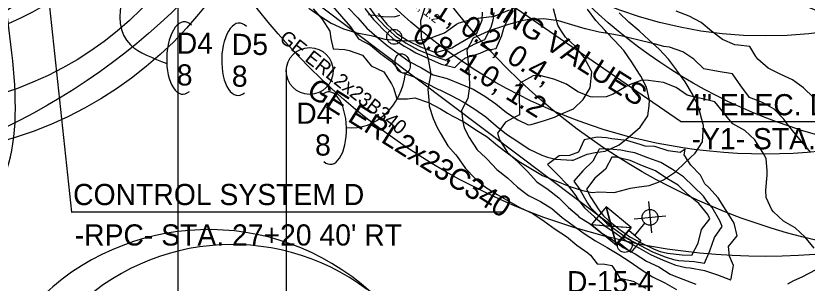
# Model space of a CAD drawing. Extents: x 1638506 to 1658005, y 834807 to 846788.
# Drawn here: x 1641459.3 to 1641907.6, y 841855.2 to 842006.7 of the extents above; entities that cross this region are included whole.
import ezdxf

# ---------------------------------------------------------------- set-up
doc = ezdxf.new("R2010")
doc.units = 0
for name, color, linetype in [('Default', 7, 'Continuous'), ('Old_Level_1', 7, 'Continuous'), ('Old_Level_4', 7, 'Continuous'), ('Scratch_Level_0', 7, 'Continuous'), ('Sheet North Arrow CELL', 7, 'Continuous')]:
    doc.layers.add(name, color=color, linetype=linetype)

msp = doc.modelspace()

# ---------------------------------------------------------------- linework, layer by layer
at = {"layer": 'Default'}
for p, q in [((1641835.95, 841946.87), (1641653.59, 842072.66)), ((1641476.47, 842029.41), (1641490.79, 841895.46)), ((1641631.71, 842012.42), (1641796.51, 841888.28)), ((1641835.95, 841946.87), (1642068.57, 841946.87)), ((1641793.84, 841898.43), (1641799.54, 841876.75)), ((1641817.8, 841901.45), (1641819.4, 841883.64)), ((1641490.78, 841895.57), (1641734.87, 841895.57)), ((1641809.71, 841891.74), (1641827.51, 841893.32)), ((1641809.99, 841882.27), (1641815.74, 841889.13)), ((1641814.1, 841892.13), (1641814.1, 841892.13)), ((1641818.61, 841892.56), (1641818.61, 841892.56)), ((1641785.52, 841888.49), (1641807.86, 841886.69))]:
    msp.add_line(p, q, dxfattribs=at)
for points in [[(1641785.52, 841888.49), (1641799.54, 841876.75), (1641807.86, 841886.69), (1641793.84, 841898.43)], [(1641796.69, 841887.59), (1641793.84, 841898.43), (1641785.52, 841888.49)], [(1641796.69, 841887.59), (1641807.86, 841886.69), (1641799.54, 841876.75)], [(1641800.84, 841878.3), (1641806.56, 841885.14), (1641813.42, 841879.4), (1641807.7, 841872.56)]]:
    msp.add_lwpolyline(points, close=True, dxfattribs=at)
msp.add_circle((1641818.59, 841892.53), 4.47, dxfattribs=at)
for centre, major_axis, ratio, start_param, end_param in [((1641554.37, 841982.82), (-0.49, -20.52), 0.466223, 2.710831, 4.712389), ((1641585.55, 841982.14), (-0.49, -20.52), 0.466223, 2.710831, 4.712389), ((1641554.37, 841982.82), (-0.49, -20.52), 0.466223, 4.712389, 6.681485), ((1641585.55, 841982.14), (-0.49, -20.52), 0.466223, 4.712389, 6.681485), ((1641650.43, 841977.68), (3.78, 34.34), 0.862742, 3.141593, 4.712389), ((1641637.08, 841943.11), (0.49, -20.52), 0.466223, 1.570796, 3.572354), ((1641637.08, 841943.11), (0.49, -20.52), 0.466223, 5.884886, 7.853982)]:
    msp.add_ellipse(centre, major_axis=major_axis, ratio=ratio, start_param=start_param, end_param=end_param, dxfattribs=at)
msp.add_ellipse((1641678.49, 841979.71), major_axis=(-1.72, 5.4), ratio=0.730797, dxfattribs=at)
for points in [[(1641534.97, 842055.74), (1641524.28, 841990.28), (1641544.84, 841979.79)], [(1641404.81, 841880.06), (1641436.37, 841894.52), (1641452.71, 842018.89)]]:
    msp.add_spline(points, degree=3, dxfattribs=at)
at = {"layer": 'Old_Level_1'}
for points in [[(1641627.73, 842010.67), (1641632.89, 842004.85), (1641637.26, 841998.04), (1641637.7, 841993.92), (1641639.14, 841988.05), (1641645.63, 841987.68), (1641648.11, 841987.08), (1641655.73, 841984.39), (1641660.7, 841978.33), (1641667.75, 841974.93), (1641672.17, 841968.17), (1641673.34, 841965.9), (1641675.23, 841959.68), (1641681.27, 841959.66), (1641685.37, 841960.21), (1641693.03, 841957.57), (1641699.9, 841953.93), (1641703.85, 841951.64), (1641706.55, 841950.02), (1641713.43, 841946.39), (1641719.85, 841942.18), (1641726.38, 841938.11), (1641732.3, 841933.26), (1641738.35, 841928.57), (1641744.57, 841924.1), (1641751.15, 841920.1), (1641757.76, 841916.13), (1641765.15, 841913.16), (1641765.21, 841913.14), (1641772.61, 841910.26), (1641780.3, 841907.66), (1641785.88, 841906.61), (1641789.51, 841907.01), (1641798.28, 841906.6), (1641799.07, 841906.79), (1641807.57, 841909.03), (1641811.07, 841909.67), (1641818.11, 841910.47), (1641822.9, 841912.34), (1641826.26, 841913.8), (1641832.96, 841918.26), (1641838.52, 841923.62), (1641844.21, 841928.87), (1641848.36, 841935.34), (1641848.84, 841944.7)], [(1641638.72, 842012.27), (1641643.78, 842006.33), (1641648.96, 842000.53), (1641653.38, 841993.78), (1641660.26, 841990.16), (1641666.1, 841985.2), (1641672.29, 841980.7), (1641677.44, 841974.87), (1641685.04, 841972.17), (1641691.89, 841968.5), (1641698.86, 841964.99), (1641699.56, 841964.74), (1641705.89, 841961.56), (1641712.78, 841957.94), (1641719.34, 841953.91), (1641725.54, 841949.42), (1641731.37, 841944.46), (1641737.4, 841939.74), (1641743.75, 841935.45), (1641750.16, 841931.22), (1641757.24, 841927.84), (1641760.48, 841926.59), (1641765.06, 841925.42), (1641774.4, 841924.92), (1641774.98, 841924.91), (1641783.02, 841928.33), (1641787.54, 841929.25), (1641793.21, 841930.04), (1641800.4, 841933.23), (1641801.1, 841933.57), (1641807.18, 841938.53), (1641813.04, 841943.65), (1641817.39, 841949.96)], [(1641647.62, 842011.21), (1641653.01, 842005.69), (1641658.11, 841999.8), (1641663.87, 841994.75), (1641669.78, 841989.89), (1641675.9, 841985.3), (1641682.17, 841980.89), (1641689.1, 841977.33), (1641695.73, 841973.38), (1641703.63, 841971.27), (1641703.76, 841971.23), (1641711.12, 841968.2), (1641718.4, 841965.09), (1641725.06, 841961.19), (1641731.35, 841956.8), (1641737.27, 841951.96), (1641743.67, 841947.72), (1641749.51, 841944.94), (1641751.35, 841945.11), (1641758.87, 841947.31), (1641764.43, 841949.37), (1641767.1, 841950.57), (1641775.21, 841953.93), (1641780.77, 841959.29), (1641784.77, 841965.87), (1641785.63, 841974.93)], [(1641657.13, 842010.92), (1641661.95, 842004.69), (1641664.83, 842001.78), (1641667.28, 841999.09), (1641672.88, 841993.83), (1641679.31, 841989.63), (1641682.5, 841987.88), (1641686.01, 841985.78), (1641693.21, 841982.56), (1641700.37, 841979.29), (1641708.12, 841977.48), (1641710.53, 841979.84), (1641713.78, 841982.76), (1641722.47, 841985.66), (1641726.08, 841987.24), (1641731.52, 841988.28), (1641734.66, 841995.53)], [(1641658.62, 842012.82), (1641663.25, 842006.33), (1641668.51, 842000.65), (1641674.15, 841995.45), (1641680.54, 841991.19), (1641687.3, 841987.42), (1641694.7, 841984.46), (1641702.33, 841981.78), (1641702.78, 841981.68), (1641709.99, 841985.74), (1641717.37, 841989.67), (1641719.03, 841990.64), (1641725.08, 841993.34), (1641728.59, 842000.31)], [(1641785.63, 841974.93), (1641785.24, 841975.84), (1641781.28, 841983.19), (1641776.33, 841989.27), (1641770.78, 841994.58), (1641768, 841998.52), (1641766.43, 842001.43), (1641763.99, 842010.7)], [(1641817.39, 841949.96), (1641818.06, 841955.7), (1641818.29, 841958.99), (1641816.69, 841966.34), (1641813.42, 841972.55), (1641812.7, 841973.64), (1641808.29, 841980.41), (1641803.79, 841987.07), (1641798.53, 841992.75), (1641793.98, 841997.56), (1641793.23, 841998.38), (1641787.94, 842004.03), (1641783.27, 842010.48)], [(1641664.54, 842007.98), (1641669.6, 842002.03), (1641675.13, 841996.7), (1641681.63, 841992.58), (1641688.6, 841989.07), (1641696.2, 841986.36), (1641697.32, 841985.97), (1641706.25, 841988.68), (1641708.83, 841990.05), (1641713.38, 841992.8), (1641720.52, 841996.92), (1641723.48, 842004.32)], [(1641723.48, 842004.32), (1641723.62, 842008.86)], [(1641728.59, 842000.31), (1641729.77, 842004.3), (1641730.37, 842008.64)], [(1641734.66, 841995.53), (1641735.86, 841999.67), (1641737.4, 842003.11), (1641741.25, 842009.81)], [(1641848.84, 841944.7), (1641848.72, 841945.19), (1641846.21, 841954.37), (1641845.17, 841957.32), (1641842.7, 841962.29), (1641838.57, 841969.41), (1641833.85, 841975.78), (1641833.58, 841976.15), (1641829.13, 841982.16), (1641823.88, 841987.86), (1641818.09, 841992.87), (1641812.52, 841998.16), (1641806.63, 842003.06), (1641801.11, 842008.4)]]:
    msp.add_lwpolyline(points, dxfattribs=at)
for centre, radius in [((1641295.68, 842272.71), 365), ((1641995.81, 842234.97), 365), ((1641295.68, 842272.71), 307), ((1641995.81, 842234.97), 307), ((1641995.81, 842234.97), 240), ((1641673.67, 841994.83), 4.21)]:
    msp.add_circle(centre, radius, dxfattribs=at)
at = {"layer": 'Old_Level_4'}
for centre, radius in [((1641883.97, 842235.35), 365), ((1641883.97, 842235.35), 307), ((1641883.97, 842235.35), 240), ((1641393.92, 842146.92), 219), ((1641393.92, 842146.92), 193), ((1641393.92, 842146.92), 157)]:
    msp.add_circle(centre, radius, dxfattribs=at)
at = {"layer": 'Scratch_Level_0'}
for points in [[(1641625.28, 842011.1), (1641631.54, 842006.69), (1641638.02, 842002.62), (1641645.01, 841999.36), (1641652.6, 841997.06), (1641660.71, 841995.58), (1641662.18, 841995.27), (1641668.47, 841993.56), (1641676.99, 841992.73), (1641680.9, 841992.53), (1641686.03, 841992.73), (1641693.3, 841993.77), (1641696.46, 841994.94), (1641702.25, 841997.17), (1641708.91, 842002.02), (1641710.43, 842002.77), (1641718.52, 842005.01), (1641721.09, 842005.36), (1641730.51, 842006.51), (1641730.98, 842006.71), (1641739.09, 842010.14)], [(1641690.99, 842011.4), (1641688.53, 842003.92), (1641688.94, 841995.12), (1641688.96, 841994.61), (1641692, 841985.62), (1641692.8, 841983.15), (1641694.28, 841974.89), (1641694.26, 841973.19), (1641692.77, 841965.09), (1641693.27, 841958.91), (1641693.57, 841955.55), (1641695.79, 841948.55), (1641697.83, 841943.83), (1641699.7, 841940.4), (1641704.13, 841933.08), (1641708.39, 841928.15), (1641709.31, 841926.95), (1641714.15, 841920.28), (1641719.51, 841914.43), (1641725.47, 841909.54), (1641731.95, 841905.46), (1641738.64, 841901.73), (1641745.24, 841897.87), (1641752.25, 841894.63), (1641758.61, 841890.38), (1641764.79, 841885.84), (1641771.22, 841881.7), (1641777.18, 841876.81), (1641783.46, 841872.41), (1641784.84, 841871), (1641788.59, 841866.21), (1641793, 841865.87), (1641796.95, 841865.13), (1641799.33, 841861.89), (1641801.54, 841858.06), (1641807.49, 841856.75), (1641809.36, 841856.11), (1641816.03, 841852.36)], [(1641659.17, 842007.5), (1641667.46, 842006.32), (1641673.64, 842006.13), (1641676.96, 842007.05)], [(1641911.17, 841960.46), (1641905.55, 841965.9), (1641899.35, 841970.4), (1641892.34, 841973.62), (1641885.49, 841977.11), (1641879.67, 841982.22), (1641878.62, 841983.72), (1641875.16, 841989.42), (1641868.53, 841990.08), (1641866.72, 841990.37), (1641859.6, 841993.41), (1641853.49, 841998.07), (1641847.55, 842002.99), (1641840.81, 842006.64), (1641833.47, 842009.35)], [(1641909.62, 841929.28), (1641904.49, 841935.47), (1641899.41, 841941.78), (1641896.23, 841945.53), (1641894.43, 841948.22), (1641888.91, 841953.82), (1641882.29, 841957.66), (1641874.99, 841960.42), (1641870.11, 841967.02), (1641865.32, 841973.78), (1641857.16, 841975.17), (1641849.09, 841976.72), (1641843.44, 841982.1), (1641837.12, 841986.41), (1641829.68, 841988.97), (1641826.48, 841989.42), (1641821.72, 841990.67), (1641813.84, 841992.51), (1641806.03, 841994.46), (1641803.02, 841995.14), (1641798.09, 841996.21), (1641789.89, 841997.55), (1641781.99, 841999.35), (1641781.95, 841999.36), (1641774.4, 842001.65), (1641766.82, 842003.98), (1641758.51, 842005.07), (1641758.47, 842005.07), (1641749.06, 842004.48), (1641746.03, 842003.89), (1641738.36, 842001.83), (1641736.08, 842001.11), (1641726.88, 841997.95), (1641726.79, 841997.92), (1641718.42, 841994.15), (1641714.85, 841987.35), (1641715.58, 841980), (1641715.72, 841977.77), (1641716.37, 841968.32), (1641716.34, 841966.85), (1641715.48, 841959.84), (1641711.8, 841953.12), (1641712.62, 841946.57), (1641713.23, 841943.18), (1641716.07, 841937.69), (1641720.73, 841930.72), (1641725.38, 841926.49), (1641726.42, 841925.41), (1641731.79, 841919.58), (1641737.91, 841914.94), (1641743.61, 841909.63), (1641749.69, 841904.93), (1641756.56, 841901.49), (1641763.04, 841897.43), (1641768.93, 841892.42), (1641775.15, 841887.94), (1641781.24, 841883.25), (1641787.77, 841879.27), (1641794.36, 841875.37), (1641800.86, 841871.35), (1641807.3, 841867.22), (1641813.67, 841862.97), (1641820.09, 841858.8), (1641826.95, 841855.35), (1641833.68, 841851.68)], [(1641911.67, 841875.08), (1641906.51, 841881.24), (1641900.76, 841886.47), (1641894.17, 841890.36), (1641888.5, 841895.71), (1641887.67, 841896.68), (1641884.49, 841903.7), (1641884.23, 841907.89), (1641885.04, 841916.42), (1641885.01, 841918.89), (1641884.38, 841925.87), (1641882.5, 841929.26), (1641877.97, 841936.43), (1641872.26, 841941.71), (1641865.57, 841945.44), (1641863.19, 841948.24), (1641860.48, 841951.73), (1641855.39, 841958), (1641847.53, 841959.88), (1641843.22, 841960.81), (1641839.67, 841961.74), (1641833.41, 841966.16), (1641826.17, 841969.02), (1641817.75, 841970), (1641813.88, 841970.23), (1641807.31, 841967.78), (1641805.07, 841966.73), (1641797.73, 841962.32), (1641793.85, 841960.74), (1641786.14, 841960.57), (1641784.9, 841960.9), (1641777.63, 841963.69), (1641771.27, 841967.95), (1641764.07, 841970.87), (1641756.28, 841972.86), (1641752.44, 841972.74), (1641744.81, 841968.5), (1641744.56, 841959.62), (1641744.71, 841954.48), (1641744.58, 841950.57), (1641741.2, 841948.89), (1641736.83, 841946.41), (1641732.21, 841940.27), (1641733.34, 841936.4), (1641737.84, 841929.2), (1641743.67, 841924.1), (1641743.94, 841923.85), (1641749.24, 841918.58), (1641754.56, 841912.67), (1641760.83, 841908.27), (1641766.88, 841903.53), (1641772.52, 841898.11), (1641777.26, 841893.85), (1641778.22, 841892.82), (1641784.78, 841888.88), (1641790.69, 841883.91), (1641797.19, 841879.88), (1641803.38, 841875.34), (1641810.14, 841871.73), (1641816.59, 841867.61), (1641823.63, 841864.43), (1641830.02, 841860.23), (1641831.36, 841859.81), (1641837.26, 841857.37), (1641844.58, 841854.64)], [(1641864.33, 841857.14), (1641864.61, 841857.74), (1641865.98, 841865.14), (1641863.56, 841870.43), (1641863.06, 841876.01), (1641868.02, 841881.93), (1641866.3, 841889.15), (1641863.49, 841893.82), (1641861.76, 841896.3), (1641857.23, 841903.47), (1641851.88, 841909.33), (1641849.71, 841911.53), (1641847.28, 841916.38), (1641841.79, 841922.03), (1641838.03, 841927.92), (1641838.47, 841931.11), (1641835.78, 841929.33), (1641828.84, 841930.17), (1641821.38, 841932.67), (1641815.95, 841932.77), (1641813.03, 841933.78), (1641805.43, 841936.06), (1641797.01, 841937.05), (1641794.03, 841937.53), (1641788.6, 841938.04), (1641781.35, 841936.47), (1641778.16, 841929.44), (1641772.91, 841927.47), (1641767.09, 841927.36), (1641761.01, 841922.92), (1641760.59, 841922.42), (1641760.64, 841922.34), (1641766.23, 841916.86), (1641771.7, 841911.18), (1641776.63, 841904.66), (1641777.85, 841902.52), (1641781.41, 841897.89), (1641787.2, 841892.73), (1641793.07, 841887.69), (1641799.34, 841883.28), (1641805.61, 841878.9), (1641812.29, 841875.14), (1641818.97, 841871.39), (1641826.05, 841868.28), (1641833.21, 841865.3), (1641838.93, 841864.09), (1641841.38, 841863.91), (1641849.39, 841862.29), (1641856.88, 841859.82), (1641864.24, 841857.15), (1641864.33, 841857.14)], [(1641859.52, 841887.28), (1641858.12, 841890.52), (1641853.84, 841898.08), (1641850.88, 841901.76), (1641848.88, 841904.56), (1641843.24, 841909.96), (1641837.67, 841915.47), (1641831.3, 841919.71), (1641824.72, 841923.62), (1641817.34, 841926.26), (1641810.03, 841929), (1641806.63, 841929.6), (1641802.04, 841930.67), (1641793.37, 841931.26), (1641789.85, 841931.12), (1641786.13, 841924.42), (1641780.48, 841918.94), (1641775.39, 841913.1), (1641778.88, 841908.23), (1641783.1, 841900.57), (1641784.94, 841898.06), (1641788.38, 841894.59), (1641794.03, 841889.22), (1641800.18, 841884.63), (1641806.41, 841880.17), (1641813.13, 841876.48), (1641819.93, 841872.92), (1641827.22, 841870.15), (1641831.83, 841868.55), (1641834.9, 841867.98), (1641843.63, 841867.49), (1641849.53, 841866.45), (1641852.59, 841873.57), (1641855.09, 841881.03), (1641859.52, 841887.28)], [(1641852.45, 841891.73), (1641851.3, 841894.04), (1641846.2, 841900.3), (1641840.31, 841905.31), (1641834.65, 841910.67), (1641828.07, 841914.58), (1641821.7, 841918.82), (1641814.41, 841921.61), (1641807.35, 841924.74), (1641799.5, 841926.63), (1641796.92, 841926.67), (1641793.41, 841919.84), (1641787.26, 841914.68), (1641782.61, 841908.56), (1641785.11, 841903.76), (1641789.68, 841896.67), (1641792.35, 841893.4), (1641795, 841890.75), (1641801.03, 841885.97), (1641807.21, 841881.44), (1641813.98, 841877.82), (1641820.9, 841874.45), (1641824.43, 841873.21), (1641828.53, 841872.22), (1641836.9, 841871.17), (1641842.32, 841870.99), (1641845.82, 841877.83), (1641847.81, 841885.61), (1641852.45, 841891.73)], [(1641896.64, 841854.88), (1641900.11, 841856.7), (1641904.81, 841858.79), (1641912.71, 841862.85), (1641913.22, 841871.57)]]:
    msp.add_lwpolyline(points, dxfattribs=at)
for centre, radius in [((1641295.75, 842272.71), 297), ((1641804.31, 841876.83), 4.21)]:
    msp.add_circle(centre, radius, dxfattribs=at)
at = {"layer": 'Sheet North Arrow CELL'}
for p, q in [((1641551.29, 840916.24), (1641551.29, 842541.24)), ((1641612.54, 841975.74), (1641612.54, 841642.24))]:
    msp.add_line(p, q, dxfattribs=at)
msp.add_circle((1641625.79, 841975.48), 13.25, dxfattribs=at)
for centre, radius, start, end in [((1641568.57, 841749.06), 136.5, 47.84, 312.3941), ((1641581.76, 841749.12), 127.95, 53.095, 308.6287)]:
    msp.add_arc(centre, radius, start, end, dxfattribs=at)

# ---------------------------------------------------------------- texts
at = {"layer": 'Default'}
for s, p in [('D4', (1641550.52, 841985.23)), ('D5', (1641581.71, 841984.55)), ('8', (1641550.52, 841967.23)), ('8', (1641581.71, 841966.55)), ('4" ELEC. DUCT, TL', (1641839.07, 841950.36)), ('D4', (1641618.19, 841945.52)), ('-Y1- STA.31+22', (1641842.16, 841931.09)), ('8', (1641628.88, 841927.52)), ('CONTROL SYSTEM D', (1641491.79, 841899.44)), ("-RPC- STA. 27+20 40' RT", (1641492.67, 841876.52)), ('D-15-4', (1641771.54, 841850.02))]:
    msp.add_text(s, height=12, dxfattribs=at).set_placement(p)
at = {"layer": 'Old_Level_1'}
for s, height, p in [('0.8, 1.0, 1.2', 5, (1641669.4, 842024.07)), ('GE ERL2x23B340', 8, (1641608.06, 841992.95))]:
    msp.add_text(s, height=height, rotation=321.8277, dxfattribs=at).set_placement(p)
at = {"layer": 'Scratch_Level_0'}
for s, p in [('0.1, 0.2, 0.4,', (1641683.82, 842014.32)), ('RING VALUES', (1641720.47, 842012.52)), ('0.8, 1.0, 1.2', (1641683.19, 841993.45)), ('GE ERL2x23C340', (1641623.31, 841962.1))]:
    msp.add_text(s, height=12, rotation=327.8202, dxfattribs=at).set_placement(p)

doc.saveas('drawing.dxf')
